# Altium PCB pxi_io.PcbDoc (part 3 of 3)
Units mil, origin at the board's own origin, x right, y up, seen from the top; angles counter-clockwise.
Board outline 6300 x 3935 mil, 2 copper layers (Top Layer, Bottom Layer); 257 components, 420 nets, 1532 pads, 239 vias.
Unrouted connection lines stored in the file: 158.
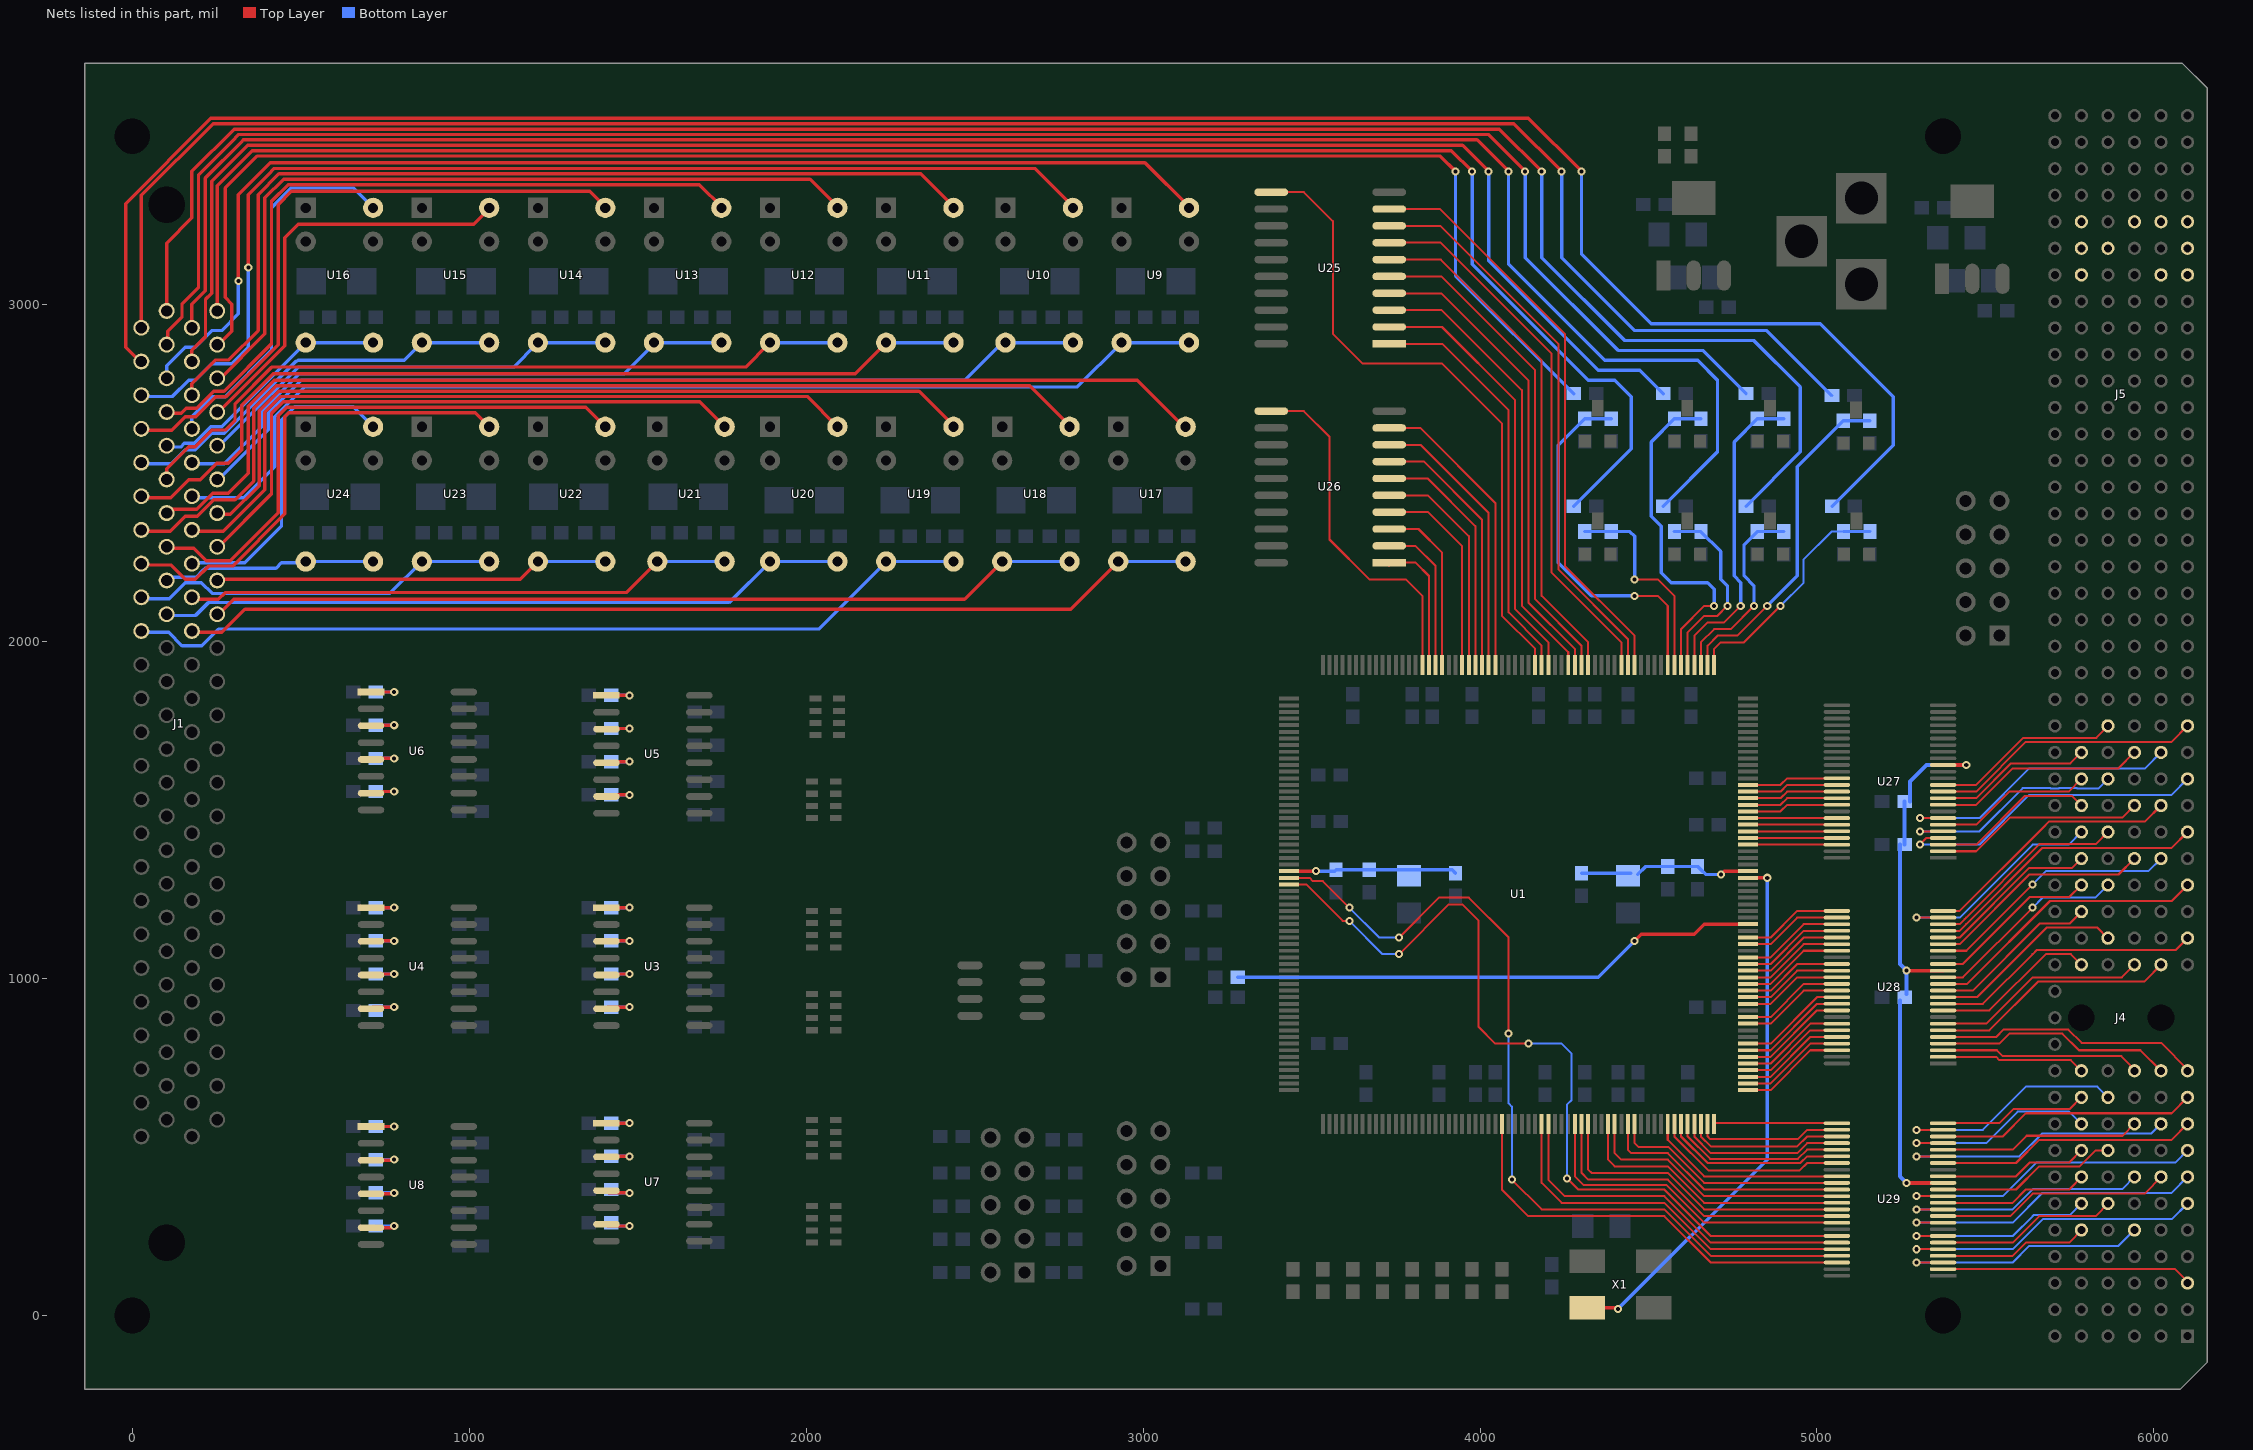
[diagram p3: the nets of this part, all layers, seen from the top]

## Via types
v1: diameter 24, hole 12, Top Layer to Bottom Layer, 232 vias
v2: diameter 36, hole 18, Top Layer to Bottom Layer, 6 vias
v3: diameter 24, hole 12, Top Layer to Bottom Layer, tented bottom, 1 vias

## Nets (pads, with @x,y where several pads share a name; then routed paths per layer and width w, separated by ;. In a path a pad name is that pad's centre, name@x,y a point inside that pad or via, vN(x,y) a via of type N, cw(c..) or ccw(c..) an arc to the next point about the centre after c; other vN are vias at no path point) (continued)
NetR11_2: R11.2 U3.7 | length 126
  Top Layer w10: U3.7@1407.48,910.63 1412.2,915.35 v1(1476.38,915.35)
  Bottom Layer w10: R11.2@1421.26,915.35 v1(1476.38,915.35)
NetR12_2: R12.2 U3.5 | length 125.3
  Top Layer w10: U3.5@1407.48,1010.63 1410.63,1013.78 v1(1476.38,1013.78)
  Bottom Layer w10: R12.2@1421.26,1013.78 v1(1476.38,1013.78)
NetR13_2: R13.2 U3.3 | length 124.7
  Top Layer w10: U3.3@1407.48,1110.63 1409.05,1112.2 v1(1476.38,1112.2)
  Bottom Layer w10: R13.2@1421.26,1112.2 v1(1476.38,1112.2)
NetR14_2: R14.2 U3.1 | length 124
  Top Layer w10: U3.1@1407.48,1210.63 v1(1476.38,1210.63)
  Bottom Layer w10: R14.2@1421.26,1210.63 v1(1476.38,1210.63)
NetR19_2: R19.2 U4.7 | length 130
  Top Layer w10: U4.7@708.66,910.63 713.39,915.35 v1(777.56,915.35)
  Bottom Layer w10: R19.2@722.44,905.51 732.28,915.35 v1(777.56,915.35)
NetR20_2: R20.2 U4.5 | length 125.3
  Top Layer w10: U4.5@708.66,1010.63 711.81,1013.78 v1(777.56,1013.78)
  Bottom Layer w10: R20.2@722.44,1013.78 v1(777.56,1013.78)
NetR21_2: R21.2 U4.3 | length 124.7
  Top Layer w10: U4.3@708.66,1110.63 710.24,1112.2 v1(777.56,1112.2)
  Bottom Layer w10: R21.2@722.44,1112.2 v1(777.56,1112.2)
NetR22_2: R22.2 U4.1 | length 124
  Top Layer w10: U4.1@708.66,1210.63 v1(777.56,1210.63)
  Bottom Layer w10: R22.2@722.44,1210.63 v1(777.56,1210.63)
NetR27_2: R27.2 U5.7 | length 119.3
  Top Layer w10: U5.7@1412.2,1545.28 v1(1476.38,1545.28)
  Bottom Layer w10: R27.2@1421.26,1545.28 v1(1476.38,1545.28)
NetR28_2: R28.2 U5.5 | length 120.9
  Top Layer w10: U5.5@1410.63,1643.7 v1(1476.38,1643.7)
  Bottom Layer w10: R28.2@1421.26,1643.7 v1(1476.38,1643.7)
NetR29_2: R29.2 U5.3 | length 124.7
  Top Layer w10: U5.3@1407.48,1740.55 1409.06,1742.13 v1(1476.38,1742.13)
  Bottom Layer w10: R29.2@1421.26,1742.13 v1(1476.38,1742.13)
NetR30_2: R30.2 U5.1 | length 124
  Top Layer w10: U5.1@1407.48,1840.55 v1(1476.38,1840.55)
  Bottom Layer w10: R30.2@1421.26,1840.55 v1(1476.38,1840.55)
NetR35_2: R35.2 U6.7 | length 126
  Top Layer w10: U6.7@708.66,1550.39 713.39,1555.12 v1(777.56,1555.12)
  Bottom Layer w10: R35.2@722.44,1555.12 v1(777.56,1555.12)
NetR36_2: R36.2 U6.5 | length 125.3
  Top Layer w10: U6.5@708.66,1650.39 711.81,1653.54 v1(777.56,1653.54)
  Bottom Layer w10: R36.2@722.44,1653.54 v1(777.56,1653.54)
NetR37_2: R37.2 U6.3 | length 124.7
  Top Layer w10: U6.3@708.66,1750.39 710.24,1751.97 v1(777.56,1751.97)
  Bottom Layer w10: R37.2@722.44,1751.97 v1(777.56,1751.97)
NetR38_2: R38.2 U6.1 | length 124
  Top Layer w10: U6.1@708.66,1850.39 v1(777.56,1850.39)
  Bottom Layer w10: R38.2@722.44,1850.39 v1(777.56,1850.39)
NetR45_2: R45.2 U7.7 | length 130.2
  Top Layer w10: U7.7@1407.48,270.87 1412.6,265.75 v1(1476.38,265.75)
  Bottom Layer w10: R45.2@1421.26,275.59 1431.1,265.75 v1(1476.38,265.75)
NetR48_2: R48.2 U7.5 | length 130.9
  Top Layer w10: U7.5@1407.48,370.87 1414.17,364.17 v1(1476.38,364.17)
  Bottom Layer w10: R48.2@1421.26,374.02 1431.1,364.17 v1(1476.38,364.17)
NetR51_2: R51.2 U7.3 | length 124.7
  Top Layer w10: U7.3@1407.48,470.87 1409.06,472.44 v1(1476.38,472.44)
  Bottom Layer w10: R51.2@1421.26,472.44 v1(1476.38,472.44)
NetR54_2: R54.2 U7.1 | length 124
  Top Layer w10: U7.1@1407.48,570.87 v1(1476.38,570.87)
  Bottom Layer w10: R54.2@1421.26,570.87 v1(1476.38,570.87)
NetR61_2: R61.2 U8.7 | length 126
  Top Layer w10: U8.7@708.66,261.02 772.83,261.02 v1(777.56,265.75)
  Bottom Layer w10: R61.2@722.44,265.75 v1(777.56,265.75)
NetR64_2: R64.2 U8.5 | length 125.3
  Top Layer w10: U8.5@708.66,361.02 774.41,361.02 v1(777.56,364.17)
  Bottom Layer w10: R64.2@722.44,364.17 v1(777.56,364.17)
NetR67_2: R67.2 U8.3 | length 122.4
  Top Layer w10: U8.3@708.66,461.02 v1@775.98,461.02
  Bottom Layer w10: R67.2@722.44,462.6 v1(777.56,462.6)
NetR70_2: R70.2 U8.1 | length 124
  Top Layer w10: U8.1@708.66,561.02 v1(777.56,561.02)
  Bottom Layer w10: R70.2@722.44,561.02 v1(777.56,561.02)
NetU1_153: U1.153 X1.3 | length 1613
  Top Layer w10: X1.3@4317.98,23.1 4406.03,23.1 v1(4409.45,19.69) ; U1.153@4795.28,1299.21 v1(4852.36,1299.21)
  Bottom Layer w10: v1(4409.45,19.69) 4852.36,462.6 v1(4852.36,1299.21)
NSTATUS: R8.2 U1.146 | length 1579
  Top Layer w10: v1(4458.66,1112.2) 4478.35,1131.89 4635.83,1131.89 4665.35,1161.42 U1.146@4795.28,1161.42
  Bottom Layer w10: R8.2@3281.5,1003.94 4350.39,1003.94 v1(4458.66,1112.2)
O5_1_A: J1.39 U9.5 U9.6 | length 3231.4
  Bottom Layer w10: J1.39@177.17,2427.56 331.1,2427.56 423.23,2519.68 423.23,2667.32 511.81,2755.91 2805.12,2755.91 U9.5@2933.07,2883.86 ; U9.5@2936.22,2887.4 U9.6@3136.22,2887.4
O5_1_B: J1.96 U9.10 | length 3596.8
  Top Layer w10: v1(314.96,3070.87) 314.96,3326.77 397.39,3409.2 ; 393.7,3405.51 409.7,3421.51 3005.65,3421.51 U9.10@3139.76,3287.4
  Bottom Layer w10: J1.96@102.17,2777.56 102.17,2818.7 157.48,2874.02 187.01,2874.02 236.22,2923.23 265.75,2923.23 314.96,2972.44 v1(314.96,3070.87)
O5_2_A: J1.40 U10.5 U10.6 | length 2723.1
  Bottom Layer w10: J1.40@252.17,2477.56 403.54,2628.94 403.54,2677.17 501.97,2775.59 2470.47,2775.59 U10.5@2578.74,2883.86 ; U10.5@2591.73,2887.4 U10.6@2791.73,2887.4
O5_2_B: J1.95 U10.10 | length 3372.5
  Top Layer w10: v1(344.49,3110.24) 344.49,3326.77 403.54,3385.83 ; 410.91,3393.2 403.54,3385.83 ; U10.10@2795.28,3287.4 2678.38,3404.3 422.02,3404.3 403.54,3385.83
  Bottom Layer w10: J1.95@27.17,2727.56 119.29,2727.56 167.32,2775.59 187.01,2775.59 236.22,2824.8 295.28,2824.8 344.49,2874.02 v1(344.49,3110.24)
O5_3_A: J1.89 U11.5 U11.6 | length 2673.9
  Top Layer w10: J1.89@27.17,2427.56 114.57,2427.56 167.32,2480.32 201.51,2480.32 250.72,2529.53 285.43,2529.53 324.8,2568.9 324.8,2701.72 418.36,2795.28 2145.67,2795.28 U11.5@2234.25,2883.86
  Bottom Layer w10: U11.5@2237.4,2887.4 U11.6@2437.4,2887.4
O5_3_B: J1.45 U11.10 | length 2838
  Top Layer w10: J1.45@177.17,2727.56 177.17,2765.75 247.44,2836.02 286.81,2836.02 374.02,2923.23 374.02,3326.77 435.54,3388.3 2340.05,3388.3 2342.52,3385.83 U11.10@2440.94,3287.4
O5_4_A: J1.90 U12.5 U12.6 | length 2205.8
  Top Layer w10: J1.90@102.17,2477.56 102.17,2513.58 167.32,2578.74 187.01,2578.74 236.22,2627.95 275.59,2627.95 305.12,2657.48 305.12,2706.69 413.39,2814.96 1820.87,2814.96 U12.5@1889.76,2883.86
  Bottom Layer w10: U12.5@1892.91,2887.4 U12.6@2092.91,2887.4
O5_4_B: J1.46 U12.10 | length 2362.2
  Top Layer w10: J1.46@252.17,2777.56 257.87,2777.56 393.7,2913.39 393.7,3316.93 449.07,3372.3 2011.56,3372.3 2017.72,3366.14 U12.10@2096.46,3287.4
O5_5_A: J1.41 U13.5 U13.6 | length 1745
  Bottom Layer w10: J1.41@177.17,2527.56 273.62,2527.56 383.86,2637.8 383.86,2684.07 495.07,2795.28 1460.38,2795.28 1545.28,2880.17 U13.5@1545.28,2883.86 ; U13.5@1548.43,2887.4 U13.6@1748.43,2887.4
O5_5_B: J1.94 U13.10 | length 2207.4
  Top Layer w10: J1.94@102.17,2677.56 145.09,2677.56 160.47,2692.94 191.51,2692.94 241.51,2742.94 272.46,2742.94 413.39,2883.86 413.39,3307.09 462.6,3356.3 1683.07,3356.3 U13.10@1751.97,3287.4
O5_6_A: J1.42 U14.5 U14.6 | length 1271.3
  Bottom Layer w10: J1.42@255.91,2578.74 332.17,2655.01 492.13,2814.96 1131.89,2814.96 U14.5@1200.79,2883.86 ; U14.5@1203.94,2887.4 U14.6@1403.94,2887.4
O5_6_B: J1.93 U14.10 | length 1940.6
  Top Layer w10: J1.93@27.17,2627.56 117.72,2627.56 157.48,2667.32 188.52,2667.32 247.57,2726.38 278.53,2726.38 433.07,2880.92 433.07,3297.24 472.44,3336.61 1358.27,3336.61 1368.11,3326.77 ; 1366.48,3328.4 1368.11,3326.77 ; U14.10@1407.48,3287.4 1368.11,3326.77
O5_7_A: J1.91 U15.5 U15.6 | length 1176.7
  Bottom Layer w10: J1.91@27.17,2527.56 116.14,2527.56 157.48,2568.9 187.01,2568.9 236.22,2618.11 272.65,2618.11 487.57,2833.03 490.51,2833.03 492.13,2834.65 807.09,2834.65 U15.5@856.3,2883.86 ; U15.5@859.45,2887.4 U15.6@1059.45,2887.4
O5_7_B: J1.44 U15.10 | length 1251.3
  Top Layer w10: J1.44@252.25,2677.47 452.76,2877.97 452.76,3198.82 492.13,3238.19 1013.78,3238.19 U15.10@1062.99,3287.4
O5_8_A: J1.92 U16.5 U16.6 | length 734
  Bottom Layer w10: J1.92@102.17,2577.56 143.51,2577.56 154.54,2588.58 184.07,2588.58 233.28,2637.8 265.75,2637.8 505.65,2877.7 U16.5@511.81,2877.7 ; U16.5@514.96,2887.4 U16.6@714.96,2887.4
O5_8_B: J1.43 U16.10 | length 1131.2
  Bottom Layer w10: J1.43@177.17,2627.56 177.17,2667.32 236.22,2726.38 275.59,2726.38 413.39,2864.17 413.39,3287.4 472.44,3346.46 655.91,3346.46 U16.10@714.96,3287.4
O5_D1: U1.193 U25.9 | length 1743
  Top Layer w6: U25.9@3730.31,3283.86 3881.5,3283.86 4251.97,2913.39 4251.97,2224.41 4458.66,2017.72 U1.193@4458.66,1931.1
O5_D2: U1.194 U25.8 | length 1685.3
  Top Layer w6: U25.8@3730.31,3233.86 3882.28,3233.86 4232.28,2883.86 4232.28,2214.57 4438.98,2007.87 U1.194@4438.98,1931.1
O5_D3: U1.195 U25.7 | length 1631
  Top Layer w6: U25.7@3730.31,3179.13 U25.7@3732.68,3181.5 ; U25.7@3730.31,3183.86 3883.07,3183.86 4212.6,2854.33 4212.6,2204.72 4419.29,1998.03 U1.195@4419.29,1931.1
O5_D4: U1.200 U25.6 | length 1537.3
  Top Layer w6: U25.6@3730.31,3133.86 3883.86,3133.86 4183.07,2834.65 4183.07,2135.83 4320.87,1998.03 U1.200@4320.87,1931.1
O5_D5: U1.201 U25.5 | length 1479.6
  Top Layer w6: U25.5@3730.31,3083.86 3884.65,3083.86 4163.39,2805.12 4163.39,2125.98 4301.18,1988.19 U1.201@4301.18,1931.1
O5_D6: U1.202 U25.4 | length 1421.9
  Top Layer w6: U25.4@3730.31,3033.86 3885.43,3033.86 4143.7,2775.59 4143.7,2116.14 4281.5,1978.35 U1.202@4281.5,1931.1
O5_D7: U1.203 U25.3 | length 1364.2
  Top Layer w6: U25.3@3730.31,2983.86 3886.22,2983.86 4124.02,2746.06 4124.02,2106.3 4261.81,1968.5 U1.203@4261.81,1931.1
O5_D8: U1.206 U25.2 | length 1290.2
  Top Layer w6: U25.2@3730.31,2933.86 3887.01,2933.86 4104.33,2716.54 4104.33,2096.46 4202.76,1998.03 U1.206@4202.76,1931.1
O5_LE: U1.208 U25.11 | length 1922.2
  Top Layer w6: U25.11@3380.31,3333.86 3477.17,3333.86 3562.99,3248.03 3562.99,2913.39 3651.57,2824.8 3887.8,2824.8 4064.96,2647.64 4064.96,2076.77 4163.39,1978.35 U1.208@4163.39,1931.1
O5_OE: U1.207 U25.1 | length 1232.5
  Top Layer w6: U25.1@3730.31,2883.86 3887.8,2883.86 4084.65,2687.01 4084.65,2086.61 4183.07,1988.19 U1.207@4183.07,1931.1
O27_1_A: J1.31 U17.5 U17.6 | length 3032.2
  Top Layer w10: J1.31@177.17,2027.56 265.75,2027.56 285.43,2047.24 ; 285.06,2046.87 334.65,2096.46 2785.43,2096.46 U17.5@2923.23,2234.25
  Bottom Layer w10: U17.5@2926.38,2237.8 U17.6@3126.38,2237.8
O27_1_B: J1.88 U17.10 | length 3356.3
  Top Layer w10: J1.88@102.17,2377.56 117.54,2392.94 191.51,2392.94 239.51,2440.94 285.43,2440.94 344.49,2500 344.49,2698.78 421.3,2775.59 2982.28,2775.59 U17.10@3120.08,2637.8
O27_2_A: J1.32 U18.5 U18.6 | length 2596.4
  Top Layer w10: J1.32@252.17,2076.77 301.38,2125.98 2470.08,2125.98 U18.5@2581.89,2237.8
  Bottom Layer w10: U18.5@2581.89,2237.8 U18.6@2781.89,2237.8
O27_2_B: J1.87 U18.10 | length 3121.2
  Top Layer w10: J1.87@27.17,2327.56 112.99,2327.56 157.48,2372.05 193.24,2372.05 242.46,2421.26 305.12,2421.26 360.49,2476.63 360.49,2692.15 427.93,2759.59 2125.98,2759.59 ; 2133.23,2759.59 2125.98,2759.59 ; U18.10@2785.43,2637.8 2663.64,2759.59 2125.98,2759.59
O27_3_A: J1.81 U19.5 U19.6 | length 2529.9
  Bottom Layer w10: J1.81@27.17,2027.56 108.27,2027.56 147.64,1988.19 206.69,1988.19 255.91,2037.4 2037.01,2037.4 U19.5@2237.4,2237.8 U19.6@2437.4,2237.8
O27_3_B: J1.38 U19.10 | length 2514.5
  Top Layer w10: J1.38@252.17,2377.56 290.94,2377.56 376.49,2463.1 376.49,2685.52 434.56,2743.59 2335.15,2743.59 U19.10@2440.94,2637.8
O27_4_A: J1.82 U20.5 U20.6 | length 2057.1
  Bottom Layer w10: J1.82@102.17,2077.56 187.8,2077.56 226.38,2116.14 1771.26,2116.14 U20.5@1892.91,2237.8 U20.6@2092.91,2237.8
O27_4_B: J1.37 U20.10 | length 2253
  Top Layer w10: J1.37@177.17,2327.56 270.47,2327.56 393.7,2450.79 393.7,2680.11 441.18,2727.59 2003.12,2727.59 U20.10@2092.91,2637.8
O27_5_A: J1.33 U21.5 U21.6 | length 1631.5
  Top Layer w10: J1.33@177.17,2135.83 187.01,2125.98 255.91,2125.98 275.59,2145.67 1466.14,2145.67 U21.5@1558.27,2237.8
  Bottom Layer w10: U21.5@1558.27,2237.8 U21.6@1758.27,2237.8
O27_5_B: J1.36 U21.10 | length 1856.1
  Top Layer w10: J1.36@252.17,2277.56 413.39,2438.78 413.39,2677.17 447.81,2711.59 1684.47,2711.59 U21.10@1758.27,2637.8
O27_6_A: J1.34 U22.5 U22.6 | length 1169.9
  Top Layer w10: J1.34@255.91,2185.04 1151.18,2185.04 U22.5@1203.94,2237.8
  Bottom Layer w10: U22.5@1203.94,2237.8 U22.6@1403.94,2237.8
O27_6_B: J1.86 U22.10 | length 1698.6
  Top Layer w10: J1.86@102.17,2277.56 183.07,2277.56 220.22,2240.41 291.59,2240.41 433.07,2381.89 433.07,2670.27 458.4,2695.59 1346.14,2695.59 U22.10@1403.94,2637.8
O27_7_A: J1.83 U23.5 U23.6 | length 1104.7
  Bottom Layer w10: J1.83@27.17,2127.56 109.84,2127.56 157.48,2175.2 205.56,2175.2 237.82,2142.94 764.59,2142.94 U23.5@859.45,2237.8 U23.6@1059.45,2237.8
O27_7_B: J1.85 U23.10 | length 1441
  Top Layer w10: J1.85@27.17,2227.56 114.96,2227.56 157.48,2185.04 187.01,2185.04 226.38,2224.41 298.22,2224.41 452.76,2378.95 452.76,2667.32 465.02,2679.59 1017.65,2679.59 U23.10@1059.45,2637.8
O27_8_A: J1.84 U24.5 U24.6 | length 637.7
  Bottom Layer w10: J1.84@102.17,2177.56 115.8,2191.2 189.77,2191.2 209.91,2211.34 ; 213.14,2214.57 209.91,2211.34 ; U24.5@511.81,2234.25 442.91,2234.25 426.91,2218.25 216.82,2218.25 209.91,2211.34 ; U24.5@514.96,2237.8 U24.6@714.96,2237.8
O27_8_B: J1.35 U24.10 | length 931.7
  Bottom Layer w10: J1.35@183.86,2234.25 334.65,2234.25 442.91,2342.52 442.91,2657.48 482.28,2696.85 655.91,2696.85 U24.10@714.96,2637.8
O27_D1: U1.214 U26.9 | length 887.6
  Top Layer w6: U26.9@3730.31,2634.25 3822.44,2634.25 4045.28,2411.42 U1.214@4045.28,1931.1
O27_D2: U1.215 U26.8 | length 829.9
  Top Layer w6: U26.8@3730.31,2584.25 3823.23,2584.25 4025.59,2381.89 U1.215@4025.59,1931.1
O27_D3: U1.216 U26.7 | length 778
  Top Layer w6: U26.7@3730.31,2534.25 3833.86,2534.25 4005.91,2362.2 U1.216@4005.91,1931.1
O27_D4: U1.217 U26.6 | length 726
  Top Layer w6: U26.6@3730.31,2484.25 3844.49,2484.25 3986.22,2342.52 U1.217@3986.22,1931.1
O27_D5: U1.218 U26.5 | length 668.3
  Top Layer w6: U26.5@3730.31,2434.25 3845.28,2434.25 3966.54,2312.99 U1.218@3966.54,1931.1
O27_D6: U1.219 U26.4 | length 610.6
  Top Layer w6: U26.4@3730.31,2384.25 3846.06,2384.25 3946.85,2283.46 U1.219@3946.85,1931.1
O27_D7: U1.222 U26.3 | length 519.3
  Top Layer w6: U26.3@3730.31,2334.25 3817.32,2334.25 3887.8,2263.78 U1.222@3887.8,1931.1
O27_D8: U1.223 U26.2 | length 455.9
  Top Layer w6: U26.2@3730.31,2284.25 3808.27,2284.25 3868.11,2224.41 U1.223@3868.11,1931.1
O27_LE: U1.225 U26.11 | length 1059
  Top Layer w6: U26.11@3380.31,2684.25 3477.17,2684.25 3553.15,2608.27 3553.15,2303.15 3671.26,2185.04 3779.53,2185.04 3828.74,2135.83 U1.225@3828.74,1931.1
O27_OE: U1.224 U26.1 | length 398.2
  Top Layer w6: U26.1@3730.31,2234.25 3809.06,2234.25 3848.43,2194.88 U1.224@3848.43,1931.1
OC5_1: J1.97 R101.2 | length 6733.1
  Top Layer w10: J1.97@29.53,2824.8 -19.68,2874.02 -19.68,3300.19 233.33,3553.2 4143.65,3553.2 v1(4301.18,3395.67)
  Bottom Layer w10: v1(4301.18,3395.67) 4301.18,3149.61 4507.87,2942.91 5009.84,2942.91 5226.38,2726.38 5226.38,2582.68 R101.2@5045.28,2401.57
OC5_2: J1.99 R103.2 | length 5962.7
  Top Layer w10: J1.99@27.17,2951.18 27.17,3324.41 239.91,3537.15 391.61,3537.15 391.65,3537.2 4100.6,3537.2 v1(4242.13,3395.67)
  Bottom Layer w10: v1(4242.13,3395.67) 4242.13,3139.76 4458.66,2923.23 4851.56,2923.23 R103.2@5044.42,2730.37
OC5_3: J1.100 R105.2 | length 6139.3
  Top Layer w10: J1.100@102.17,3001.18 102.17,3182.87 177.17,3257.87 177.17,3395.67 302.65,3521.15 398.23,3521.15 398.28,3521.2 4057.54,3521.2 v1(4183.07,3395.67)
  Bottom Layer w10: v1(4183.07,3395.67) 4183.07,3139.76 4429.13,2893.7 4812.99,2893.7 4950.79,2755.91 4950.79,2562.99 R105.2@4789.37,2401.57
OC5_4: J1.98 R107.2 | length 5632.7
  Top Layer w10: J1.98@105.91,2901.18 105.91,2920.87 147.64,2962.6 147.64,3001.97 196.85,3051.18 196.85,3385.83 295.28,3484.25 316.17,3505.15 404.86,3505.15 404.91,3505.2 4024.33,3505.2 v1(4133.86,3395.67)
  Bottom Layer w10: v1(4133.86,3395.67) 4133.86,3139.76 4409.45,2864.17 4661.42,2864.17 R107.2@4789.37,2736.22
OC5_5: J1.49 R109.2 | length 5878
  Top Layer w10: J1.49@177.17,2951.18 177.17,3001.97 216.54,3041.34 216.54,3375.98 324.8,3484.25 329.7,3489.15 411.49,3489.15 411.53,3489.2 3897.63,3489.2 ; 3901.52,3489.2 3897.63,3489.2 ; v1(4084.65,3395.67) 3991.12,3489.2 3897.63,3489.2
  Bottom Layer w10: v1(4084.65,3395.67) 4084.65,3120.08 4370.08,2834.65 4645.67,2834.65 4704.72,2775.59 4704.72,2562.99 R109.2@4543.31,2401.57
OC5_6: J1.47 R111.2 | length 5353
  Top Layer w10: J1.47@178,2852.02 177.17,2851.18 177.17,2864.17 217.54,2904.55 217.54,3015.52 236.17,3034.14 236.17,3366.09 343.23,3473.15 418.11,3473.15 418.16,3473.2 3948.06,3473.2 v1(4025.59,3395.67)
  Bottom Layer w10: v1(4025.59,3395.67) 4025.59,3129.92 4350.39,2805.12 4474.41,2805.12 R111.2@4543.31,2736.22
OC5_7: J1.50 R113.2 | length 5474.9
  Top Layer w10: J1.50@252.17,2977.56 252.17,3352.56 324.8,3425.2 356.76,3457.15 424.74,3457.15 424.79,3457.2 3914.85,3457.2 v1(3976.38,3395.67)
  Bottom Layer w10: v1(3976.38,3395.67) 3976.38,3120.08 4320.87,2775.59 4399.61,2775.59 4448.82,2726.38 4448.82,2572.83 R113.2@4277.56,2401.57
OC5_8: J1.48 R115.2 | length 5058.4
  Top Layer w10: J1.48@252.17,2877.56 295.28,2920.67 295.28,3001.97 275.59,3021.65 275.59,3346.46 370.28,3441.15 431.37,3441.15 431.42,3441.2 3881.64,3441.2 v1(3927.17,3395.67)
  Bottom Layer w10: 3927.17,3346.46 v1(3927.17,3395.67) 3927.17,3086.61 R115.2@4277.56,2736.22
OC5_D1: C81.2 R100.1 U1.181 | length 694.5
  Top Layer w6: U1.181@4694.88,1931.1 4694.88,1978.35 4714.57,1998.03 4783.46,1998.03 v1(4891.73,2106.3)
  Bottom Layer w6: v1(4891.73,2106.3) 4960.63,2175.2 4960.63,2244.09 5043.31,2326.77 C81.2@5078.74,2326.77
  Bottom Layer w10: C81.2@5078.74,2326.77 R100.1@5157.48,2326.77
OC5_D2: C82.2 R102.1 U1.182 | length 1004.6
  Top Layer w6: U1.182@4675.2,1931.1 4675.2,1988.19 4704.72,2017.72 4763.78,2017.72 v1(4852.36,2106.3)
  Bottom Layer w10: v1(4852.36,2106.3) 4940.94,2194.88 4940.94,2518.63 C82.2@5077.88,2655.57 R102.1@5156.62,2655.57
OC5_D3: C83.2 R104.1 U1.183 | length 597
  Top Layer w6: U1.183@4655.51,1931.1 4655.51,1998.03 4694.88,2037.4 4744.09,2037.4 v1(4812.99,2106.3)
  Bottom Layer w10: v1(4812.99,2106.3) 4812.99,2165.35 4783.46,2194.88 4783.46,2287.4 C83.2@4822.83,2326.77 R104.1@4901.57,2326.77
OC5_D4: C84.2 R106.1 U1.184 | length 931.7
  Top Layer w6: U1.184@4635.83,1931.1 4635.83,2017.72 4675.2,2057.09 4724.41,2057.09 v1(4773.62,2106.3)
  Bottom Layer w10: v1(4773.62,2106.3) 4773.62,2175.2 4753.94,2194.88 4753.94,2592.52 C84.2@4822.83,2661.42 R106.1@4901.57,2661.42
OC5_D5: C85.2 R108.1 U1.185 | length 579
  Top Layer w6: U1.185@4616.14,1931.1 4616.14,2027.56 4665.35,2076.77 4704.72,2076.77 v1(4734.25,2106.3)
  Bottom Layer w10: C85.2@4576.77,2326.77 R108.1@4655.51,2326.77 4714.57,2267.72 4714.57,2185.04 4734.25,2165.35 v1(4734.25,2106.3)
OC5_D6: C86.2 R110.1 U1.186 | length 1036.5
  Top Layer w6: U1.186@4596.46,1931.1 4596.46,2037.4 4665.35,2106.3 v1(4694.88,2106.3)
  Bottom Layer w10: R110.1@4655.51,2661.42 C86.2@4576.77,2661.42 4507.87,2592.52 4507.87,2372.05 4537.4,2342.52 4537.4,2204.72 4566.93,2175.2 4675.2,2175.2 4694.88,2155.51 v1(4694.88,2106.3)
OC5_D7: C87.2 R112.1 U1.187 | length 624.5
  Top Layer w6: v1(4458.66,2185.04) 4527.56,2185.04 4576.77,2135.83 U1.187@4576.77,1931.1
  Bottom Layer w10: C87.2@4311.02,2326.77 R112.1@4389.76,2326.77 4444.88,2326.77 4458.66,2312.99 v1(4458.66,2185.04)
OC5_D8: C88.2 R114.1 U1.188 | length 1091.5
  Top Layer w6: v1(4458.66,2135.83) 4527.56,2135.83 4557.09,2106.3 U1.188@4557.09,1931.1
  Bottom Layer w10: R114.1@4389.76,2661.42 C88.2@4311.02,2661.42 4232.28,2582.68 4232.28,2234.25 4330.71,2135.83 v1(4458.66,2135.83)
P_AD0: U1.167 U27.36 | length 271.9
  Top Layer w6: U1.167@4795.28,1574.8 4891.73,1574.8 4911.42,1594.49 U27.36@5059.06,1594.49
P_AD1: U1.166 U27.37 | length 271.9
  Top Layer w6: U1.166@4795.28,1555.12 4891.73,1555.12 4911.42,1574.8 U27.37@5059.06,1574.8
P_AD2: U1.165 U27.38 | length 271.9
  Top Layer w6: U1.165@4795.28,1535.43 4891.73,1535.43 4911.42,1555.12 U27.38@5059.06,1555.12
P_AD3: U1.164 U27.39 | length 271.9
  Top Layer w6: U1.164@4795.28,1515.75 4891.73,1515.75 4911.42,1535.43 U27.39@5059.06,1535.43
P_AD4: U1.163 U27.40 | length 271.9
  Top Layer w6: U1.163@4795.28,1496.06 4891.73,1496.06 4911.42,1515.75 U27.40@5059.06,1515.75
P_AD5: U1.162 U27.42 | length 263.8
  Top Layer w6: U1.162@4795.28,1476.38 U27.42@5059.06,1476.38
P_AD6: U1.161 U27.43 | length 263.8
  Top Layer w6: U1.161@4795.28,1456.69 U27.43@5059.06,1456.69
P_AD7: U1.160 U27.44 | length 263.8
  Top Layer w6: U1.160@4795.28,1437.01 U27.44@5059.06,1437.01
P_AD8: U1.158 U27.46 | length 263.8
  Top Layer w6: U1.158@4795.28,1397.64 U27.46@5059.06,1397.64
P_AD9: U1.144 U28.25 | length 296.4
  Top Layer w6: U1.144@4795.28,1122.05 4862.2,1122.05 4940.94,1200.79 U28.25@5059.06,1200.79
P_AD10: U1.143 U28.26 | length 296.4
  Top Layer w6: U1.143@4795.28,1102.36 4862.2,1102.36 4940.94,1181.1 U28.26@5059.06,1181.1
P_AD11: U1.141 U28.27 | length 304.5
  Top Layer w6: U1.141@4795.28,1062.99 4862.2,1062.99 4960.63,1161.42 U28.27@5059.06,1161.42
P_AD12: U1.140 U28.28 | length 304.5
  Top Layer w6: U1.140@4795.28,1043.31 4862.2,1043.31 4960.63,1141.73 U28.28@5059.06,1141.73
P_AD13: U1.139 U28.29 | length 304.5
  Top Layer w6: U1.139@4795.28,1023.62 4862.2,1023.62 4960.63,1122.05 U28.29@5059.06,1122.05
P_AD14: U1.138 U28.30 | length 304.5
  Top Layer w6: U1.138@4795.28,1003.94 4862.2,1003.94 4960.63,1102.36 U28.30@5059.06,1102.36
P_AD15: U1.137 U28.31 | length 304.5
  Top Layer w6: U1.137@4795.28,984.25 4862.2,984.25 4960.63,1082.68 U28.31@5059.06,1082.68
P_AD16: U1.122 U28.45 | length 312.7
  Top Layer w6: U1.122@4795.28,688.98 4862.2,688.98 4980.31,807.09 5000,807.09 U28.45@5059.06,807.09
P_AD17: U1.123 U28.44 | length 312.7
  Top Layer w6: U1.123@4795.28,708.66 4862.2,708.66 4980.31,826.77 5000,826.77 U28.44@5059.06,826.77
P_AD18: U1.124 U28.43 | length 312.7
  Top Layer w6: U1.124@4795.28,728.35 4862.2,728.35 4980.31,846.46 5000,846.46 U28.43@5059.06,846.46
P_AD19: U1.120 U29.25 | length 364.2
  Top Layer w6: U1.120@4694.88,570.87 U29.25@5059.06,570.87
P_AD20: U1.119 U29.26 | length 435.8
  Top Layer w6: U1.119@4675.2,568.9 4675.2,531.5 4682.88,523.81 4943.1,523.81 4970.47,551.18 U29.26@5059.06,551.18
P_AD21: U1.118 U29.27 | length 455.6
  Top Layer w6: U1.118@4655.51,568.9 4655.51,531.5 4685.04,501.97 4940.94,501.97 4970.47,531.5 U29.27@5049.21,531.5
P_AD22: U1.117 U29.28 | length 493.2
  Top Layer w6: U1.117@4635.83,568.9 4635.83,531.5 4685.04,482.28 4940.94,482.28 4970.47,511.81 4980.31,511.81 U29.28@5059.06,511.81
P_AD23: U1.116 U29.29 | length 519.3
  Top Layer w6: U1.116@4616.14,568.9 4616.14,531.5 4682.88,464.76 4943.1,464.76 4970.47,492.13 4980.31,492.13 U29.29@5059.06,492.13
P_AD24: U1.113 U29.33 | length 594.1
  Top Layer w6: U1.113@4557.09,568.9 4557.09,521.65 4665.35,413.39 4980.31,413.39 U29.33@5059.06,413.39
P_AD25: U1.108 U29.34 | length 706.4
  Top Layer w6: U1.108@4458.66,568.9 4458.66,511.81 4469.92,500.55 4558.07,500.55 4664.92,393.7 4980.31,393.7 U29.34@5059.06,393.7
P_AD26: U1.107 U29.35 | length 745.8
  Top Layer w6: U1.107@4438.98,568.9 4438.98,492.13 4448.82,482.28 4557.09,482.28 4665.35,374.02 4980.31,374.02 U29.35@5059.06,374.02
P_AD27: U1.105 U29.36 | length 799.1
  Top Layer w6: U1.105@4399.61,568.9 4399.61,482.28 4419.29,462.6 4557.09,462.6 4665.35,354.33 4980.31,354.33 U29.36@5059.06,354.33
P_AD28: U1.104 U29.37 | length 838.4
  Top Layer w6: U1.104@4379.92,568.9 4379.92,462.6 4399.61,442.91 4557.09,442.91 4665.35,334.65 4980.31,334.65 U29.37@5059.06,334.65
P_AD29: U1.101 U29.38 | length 922.9
  Top Layer w6: U1.101@4320.87,568.9 4320.87,433.07 4330.71,423.23 4557.09,423.23 4665.35,314.96 4980.31,314.96 U29.38@5059.06,314.96
P_AD30: U1.100 U29.39 | length 956.5
  Top Layer w6: U1.100@4301.18,568.9 4301.18,423.23 4320.87,403.54 4557.09,403.54 4665.35,295.28 4980.31,295.28 U29.39@5059.06,295.28
P_AD31: U1.99 U29.40 | length 990.1
  Top Layer w6: U1.99@4281.5,568.9 4281.5,413.39 4306.81,388.07 4552.87,388.07 4665.35,275.59 4980.31,275.59 U29.40@5059.06,275.59
P_CBE0: U1.159 U27.45 | length 263.8
  Top Layer w6: U1.159@4795.28,1417.32 U27.45@5059.06,1417.32
P_CBE1: U1.136 U28.33 | length 296.4
  Top Layer w6: U1.136@4795.28,964.57 4862.2,964.57 4940.94,1043.31 U28.33@5059.06,1043.31
P_CBE2: U1.121 U28.46 | length 312.7
  Top Layer w6: U1.121@4795.28,669.29 4862.2,669.29 4980.31,787.4 5000,787.4 U28.46@5059.06,787.4
P_CBE3: U1.114 U29.31 | length 570.4
  Top Layer w6: U1.114@4576.77,568.9 4576.77,531.5 4677.35,430.91 4948.63,430.91 4970.47,452.76 4980.31,452.76 U29.31@5059.06,452.76
P_CLK: U1.29 U29.42 | length 2600.6
  Top Layer w6: U1.29@3433.07,1279.53 3484.25,1279.53 3592.52,1171.26 v1(3612.2,1171.26) ; v1(3759.84,1072.83) 3907.48,1220.47 3946.85,1220.47 3996.06,1171.26 3996.06,856.3 4045.28,807.09 v1(4143.7,807.09) ; v1(4258.6,406.76) 4291.34,374.02 4547.24,374.02 4685.04,236.22 4980.31,236.22 U29.42@5059.06,236.22
  Bottom Layer w6: v1(3612.2,1171.26) 3710.63,1072.83 v1(3759.84,1072.83) ; v1(4143.7,807.09) 4242.13,807.09 4271.65,777.56 4271.65,639.76 4258.6,626.71 v1(4258.6,406.76)
P_DEVSEL: U1.128 U28.38 | length 320.9
  Top Layer w6: U1.128@4795.28,807.09 4862.2,807.09 5000,944.88 5019.69,944.88 U28.38@5059.06,944.88
P_FRAME: U1.125 U28.42 | length 312.7
  Top Layer w6: U1.125@4795.28,748.03 4862.2,748.03 4980.31,866.14 5000,866.14 U28.42@5059.06,866.14
P_GNT: U1.94 U29.44 | length 1132.7
  Top Layer w6: U1.94@4183.07,568.9 4183.07,393.7 4242.13,334.65 4547.24,334.65 4685.04,196.85 4980.31,196.85 U29.44@5059.06,196.85
P_IDSEL: U1.115 U29.30 | length 540.8
  Top Layer w6: U1.115@4596.46,568.9 4596.46,531.5 4675.2,452.76 4950.79,452.76 4970.47,472.44 4980.31,472.44 U29.30@5059.06,472.44
P_INTA: U1.88 U29.46 | length 1280.7
  Top Layer w6: U1.88@4064.96,568.9 4064.96,374.02 4143.7,295.28 4547.24,295.28 4685.04,157.48 4980.31,157.48 U29.46@5059.06,157.48 U29.46@5057.64,156.06
P_IRDY: U1.126 U28.40 | length 360.2
  Top Layer w6: U1.126@4795.28,767.72 4862.2,767.72 5000,905.51 U28.40@5059.06,905.51 5019.68,905.51
P_PAR: U1.135 U28.34 | length 296.4
  Top Layer w6: U1.135@4795.28,944.88 4862.2,944.88 4940.94,1023.62 U28.34@5059.06,1023.62
P_PERR: U1.132 U28.36 | length 304.5
  Top Layer w6: U1.132@4795.28,885.83 4862.2,885.83 4960.63,984.25 U28.36@5059.06,984.25
P_REQ: U1.95 U29.43 | length 1099.1
  Top Layer w6: U1.95@4202.76,568.9 4202.76,403.54 4251.97,354.33 4547.24,354.33 4685.04,216.54 4980.31,216.54 U29.43@5059.06,216.54
P_RST: U1.28 U29.45 | length 2603.7
  Top Layer w6: U1.28@3433.07,1299.21 3494.09,1299.21 3503.94,1289.37 3533.46,1289.37 v1(3612.2,1210.63) ; v1@3759.84,1122.05 3877.95,1240.16 3966.54,1240.16 4084.65,1122.05 v1(4084.65,836.61) ; v1(4094.49,403.54) 4183.07,314.96 4547.24,314.96 4685.04,177.17 4980.31,177.17 U29.45@5059.06,177.17
  Bottom Layer w6: v1(3612.2,1210.63) 3700.85,1121.99 v1(3759.78,1121.99) ; v1(4084.65,836.61) 4084.65,629.92 4094.49,620.08 v1(4094.49,403.54)
P_SERR: U1.134 U28.35 | length 296.4
  Top Layer w6: U1.134@4795.28,925.2 4862.2,925.2 4940.94,1003.94 U28.35@5059.06,1003.94
P_STOP: U1.131 U28.37 | length 304.5
  Top Layer w6: U1.131@4795.28,866.14 4862.2,866.14 4960.63,964.57 U28.37@5059.06,964.57
P_TRDY: U1.127 U28.39 | length 320.9
  Top Layer w6: U1.127@4795.28,787.4 4862.2,787.4 5000,925.2 5019.69,925.2 U28.39@5059.06,925.2
PXI_AD0: J4.D24 U27.12 | length 565.5
  Top Layer w6: U27.12@5374.02,1574.8 5472.44,1574.8 5612.39,1714.76 5828.93,1714.76 J4.D24@5866.14,1751.97
PXI_AD1: J4.A24 U27.11 | length 806.3
  Top Layer w6: U27.11@5374.02,1555.12 5472.44,1555.12 5620.08,1702.76 6052.36,1702.76 J4.A24@6099.61,1750
PXI_AD2: J4.E23 U27.10 | length 471.6
  Top Layer w6: U27.10@5374.02,1535.43 5472.44,1535.43 5575.79,1638.78 5752.17,1638.78 J4.E23@5784.65,1671.26
  Bottom Layer w6: J4.E23@5784.65,1671.26 J4.E23@5784.65,1675.98
PXI_AD3: J4.C23 U27.9 | length 632.5
  Top Layer w6: U27.9@5374.02,1515.75 5472.44,1515.75 5580.71,1624.02 5894.88,1624.02 J4.C23@5942.13,1671.26
PXI_AD4: J4.B23 U27.7 | length 865.4
  Top Layer w6: v1(5305.12,1476.38) U27.7@5374.02,1476.38
  Bottom Layer w6: v1(5305.12,1476.38) 5482.28,1476.38 5629.92,1624.02 5973.62,1624.02 J4.B23@6020.87,1671.26
PXI_AD5: J4.E22 U27.6 | length 466.9
  Top Layer w6: U27.6@5374.02,1456.69 5472.44,1456.69 5570.87,1555.12 5747.24,1555.12 J4.E22@5784.65,1592.52
PXI_AD6: J4.D22 U27.5 | length 708.4
  Top Layer w6: v1(5305.12,1437.01) U27.5@5374.02,1437.01
  Bottom Layer w6: v1(5305.12,1437.01) 5482.28,1437.01 5610.24,1564.96 5692.9,1564.96 5694.02,1563.83 5717.79,1563.83 5718.91,1564.96 5771.64,1564.96 5772.76,1563.83 5834.7,1563.83 J4.D22@5863.39,1592.52 J4.D22@5848.43,1592.52
PXI_AD7: J4.A22 U27.4 | length 952.3
  Top Layer w6: v1(5305.12,1397.64) 5324.8,1417.32 U27.4@5374.02,1417.32
  Bottom Layer w6: v1(5305.12,1397.64) 5482.28,1397.64 5629.92,1545.28 6052.36,1545.28 J4.A22@6099.61,1592.52
PXI_AD8: J4.C21 U27.2 | length 624.4
  Top Layer w6: U27.2@5374.02,1377.95 5472.44,1377.95 5573.02,1478.54 5906.88,1478.54 J4.C21@5942.13,1513.78
PXI_AD9: J4.B21 U28.24 | length 776.5
  Top Layer w6: U28.24@5374.02,1200.79 5423.23,1200.79 5669.36,1446.92 5688.98,1466.54 5973.62,1466.54 J4.B21@6020.87,1513.78
PXI_AD10: J4.E20 U28.23 | length 673.3
  Top Layer w6: v1(5295.28,1181.1) U28.23@5374.02,1181.1
  Bottom Layer w6: v1(5295.28,1181.1) 5423.23,1181.1 5639.76,1397.64 5747.24,1397.64 J4.E20@5784.65,1435.04
PXI_AD11: J4.D20 U28.22 | length 609.8
  Top Layer w6: U28.22@5374.02,1161.42 5423.23,1161.42 5442.91,1181.1 ; 5437.99,1176.18 5442.91,1181.1 ; J4.D20@5863.39,1435.04 5828.14,1399.8 5669.29,1399.8 5661.61,1399.8 5661.61,1399.62 5443.08,1181.1 5442.91,1181.1
PXI_AD12: J4.A20 U28.21 | length 854
  Top Layer w6: U28.21@5374.02,1141.73 5423.23,1141.73 5442.91,1161.41 ; 5437.99,1156.5 5442.91,1161.41 ; J4.A20@6099.61,1435.04 6052.36,1387.8 5669.29,1387.8 5442.91,1161.41
PXI_AD13: J4.E19 U28.20 | length 507.7
  Top Layer w6: U28.20@5374.02,1122.05 5423.23,1122.05 5628.8,1327.61 5755.96,1327.61 J4.E19@5784.65,1356.3
PXI_AD14: J4.C19 U28.19 | length 673.3
  Top Layer w6: U28.19@5374.02,1102.36 5423.23,1102.36 5629.92,1309.06 5894.88,1309.06 J4.C19@5942.13,1356.3
PXI_AD15: J4.B19 U28.18 | length 760.2
  Top Layer w6: U28.18@5374.02,1082.68 5442.91,1082.68 v1(5639.76,1279.53)
  Bottom Layer w6: v1(5639.76,1279.53) 5679.13,1318.9 5983.46,1318.9 J4.B19@6020.87,1356.3
PXI_AD16: J4.C11 U28.3 | length 600.4
  Top Layer w6: U28.3@5374.02,787.4 5533.65,787.4 5551.18,769.87 5903.35,769.87 J4.C11@5944.88,728.35 ; J4.C11@5937.01,726.38 J4.C11@5942.13,726.38
PXI_AD17: J4.B11 U28.4 | length 704.7
  Top Layer w6: U28.4@5374.02,807.09 5541.34,807.09 5570.87,836.61 5728.35,836.61 5777.56,787.4 5959.84,787.4 J4.B11@6020.87,726.38
PXI_AD18: J4.A11 U28.5 | length 792.3
  Top Layer w6: U28.5@5374.02,826.77 5531.5,826.77 5553.34,848.61 5745.87,848.61 5785.24,809.24 6021.46,809.24 J4.A11@6102.36,728.35 ; J4.A11@6094.49,726.38 J4.A11@6099.61,726.38
PXI_AD19: J4.E10 U29.24 | length 442.4
  Top Layer w6: U29.24@5374.02,570.87 5482.28,570.87 5541.34,570.87 5582.87,612.39 5749.4,612.39 J4.E10@5784.65,647.64
PXI_AD20: J4.D10 U29.23 | length 717.6
  Top Layer w6: v1(5295.28,551.18) U29.23@5374.02,551.18
  Bottom Layer w6: v1(5295.28,551.18) 5492.13,551.18 5620.08,679.13 5831.89,679.13 J4.D10@5863.39,647.64 J4.D10@5863.39,652.36
PXI_AD21: J4.A10 U29.22 | length 763.9
  Top Layer w6: U29.22@5383.86,531.5 5551.18,531.5 5620.08,600.39 6052.36,600.39 J4.A10@6099.61,647.64
PXI_AD22: J4.E9 U29.21 | length 621.9
  Top Layer w6: v1(5295.28,511.81) U29.21@5374.02,511.81
  Bottom Layer w6: v1(5295.28,511.81) 5501.97,511.81 5595.47,605.32 5748.23,605.32 J4.E9@5784.65,568.9
PXI_AD23: J4.C9 U29.20 | length 599.9
  Top Layer w6: U29.20@5374.02,492.13 5580.71,492.13 5622.24,533.65 5906.88,533.65 J4.C9@5942.13,568.9
PXI_AD24: J4.E8 U29.16 | length 442.4
  Top Layer w6: U29.16@5374.02,413.39 5590.55,413.39 5632.08,454.91 5749.4,454.91 J4.E8@5784.65,490.16
PXI_AD25: J4.D8 U29.14 | length 537.5
  Top Layer w6: U29.14@5374.02,374.02 5590.55,374.02 5659.45,442.91 5779.53,442.91 5826.77,490.16 J4.D8@5863.39,490.16
PXI_AD26: J4.A8 U29.13 | length 939.3
  Top Layer w6: v1(5295.28,354.33) U29.13@5374.02,354.33
  Bottom Layer w6: v1(5295.28,354.33) 5551.18,354.33 5651.76,454.91 6064.36,454.91 J4.A8@6099.61,490.16
PXI_AD27: J4.E7 U29.12 | length 446
  Top Layer w6: U29.12@5374.02,334.65 5580.71,334.65 5620.08,374.02 5748.03,374.02 J4.E7@5787.4,413.39
PXI_AD28: J4.C7 U29.11 | length 765.5
  Top Layer w6: v1(5295.28,314.96) U29.11@5374.02,314.96
  Bottom Layer w6: v1(5295.28,314.96) 5580.71,314.96 5641.92,376.17 5906.88,376.17 J4.C7@5942.13,411.42
PXI_AD29: J4.B7 U29.10 | length 698.5
  Top Layer w6: U29.10@5374.02,295.28 5573.02,295.28 5639.76,362.02 5972.25,362.02 J4.B7@6023.62,413.39
PXI_AD30: J4.A7 U29.9 | length 939.3
  Top Layer w6: v1(5295.28,275.59) U29.9@5374.02,275.59
  Bottom Layer w6: v1(5295.28,275.59) 5580.71,275.59 5669.29,364.17 6052.36,364.17 J4.A7@6099.61,411.42
PXI_AD31: J4.E6 U29.7 | length 618.7
  Top Layer w6: v1(5295.28,236.22) U29.7@5374.02,236.22
  Bottom Layer w6: v1(5295.28,236.22) 5580.71,236.22 5639.76,295.28 5642.71,298.22 5750.19,298.22 J4.E6@5784.65,332.68 J4.E6@5784.65,322.05
PXI_C/BE0: J4.E21 U27.3 | length 482.5
  Top Layer w6: U27.3@5374.02,1397.64 5472.44,1397.64 5617.27,1542.46 5755.96,1542.46 J4.E21@5784.65,1513.78
PXI_C/BE1: J4.E18 U28.16 | length 507.7
  Top Layer w6: U28.16@5374.02,1043.31 5433.07,1043.31 5632.08,1242.32 5749.4,1242.32 J4.E18@5784.65,1277.56
PXI_C/BE2: J4.E11 U28.2 | length 427.8
  Top Layer w6: U28.2@5374.02,767.72 5531.5,767.72 5541.34,757.87 5753.15,757.87 J4.E11@5784.65,726.38
PXI_C/BE3: J4.A9 U29.18 | length 773.7
  Top Layer w6: U29.18@5374.02,452.76 5590.55,452.76 5659.45,521.65 6052.36,521.65 J4.A9@6099.61,568.9
PXI_CLK: J4.D6 U29.6 | length 541
  Top Layer w6: U29.6@5374.02,216.54 5580.71,216.54 5659.45,295.28 5826.77,295.28 J4.D6@5866.14,334.65
PXI_CLK10: J5.E17
PXI_DEVSEL: J4.A16 U28.10 | length 809.9
  Top Layer w6: U28.10@5374.02,925.2 5492.13,925.2 5639.76,1072.83 5651.76,1084.83 6065.15,1084.83 J4.A16@6102.36,1122.05
PXI_FRAME: J4.B15 U28.6 | length 731.1
  Top Layer w6: U28.6@5374.02,846.46 5511.81,846.46 5657.29,991.94 5972.25,991.94 J4.B15@6023.62,1043.31
PXI_GNT: J4.E5 U29.4 | length 446
  Top Layer w6: U29.4@5374.02,177.17 5580.71,177.17 5620.08,216.54 5748.03,216.54 J4.E5@5787.4,255.91
PXI_IDSEL: J4.B9 U29.19 | length 844.3
  Top Layer w6: v1(5295.28,472.44) U29.19@5374.02,472.44
  Bottom Layer w6: v1(5295.28,472.44) 5600.39,472.44 5668.17,540.21 5992.18,540.21 J4.B9@6020.87,568.9
PXI_INTA: J4.A3 U29.2 | length 745.4
  Top Layer w6: U29.2@5374.02,137.8 6062.99,137.8 J4.A3@6102.36,98.43 ; J4.A3@6099.61,95.67 J4.A3@6099.61,96.46
PXI_IRDY: J4.C15 U28.7 | length 640.7
  Top Layer w6: U28.7@5374.02,866.14 5501.97,866.14 5639.76,1003.94 5904.72,1003.94 J4.C15@5942.13,1041.34
PXI_PAR: J4.D18 U28.14 | length 602.7
  Top Layer w6: U28.14@5374.02,1003.94 5433.07,1003.94 v1(5639.76,1210.63)
  Bottom Layer w6: v1(5639.76,1210.63) 5669.29,1240.16 5825.98,1240.16 J4.D18@5863.39,1277.56
PXI_PERR: J4.E17 U28.12 | length 497.3
  Top Layer w6: U28.12@5374.02,964.57 5462.6,964.57 5661.61,1163.57 5750.19,1163.57 J4.E17@5777.56,1190.94
PXI_REQ: J4.A6 U29.5 | length 939.3
  Top Layer w6: v1(5295.28,196.85) U29.5@5374.02,196.85
  Bottom Layer w6: v1(5295.28,196.85) 5580.71,196.85 5670.08,286.22 6053.15,286.22 J4.A6@6099.61,332.68
PXI_RST: J4.C5 U29.3 | length 780.9
  Top Layer w6: v1(5295.28,157.48) U29.3@5374.02,157.48
  Bottom Layer w6: v1(5295.28,157.48) 5580.71,157.48 5629.92,206.69 5894.88,206.69 J4.C5@5942.13,253.94 ; J4.C5@5942.13,243.31 J4.C5@5942.13,253.94 ; J4.C5@5946.85,253.94 J4.C5@5942.13,253.94
PXI_SERR: J4.A18 U28.13 | length 847.1
  Top Layer w6: U28.13@5374.02,984.25 5445.31,984.25 5691.38,1230.32 6052.36,1230.32 J4.A18@6099.61,1277.56
PXI_START: J5.D17
PXI_STOP: J4.D16 U28.11 | length 588
  Top Layer w6: U28.11@5374.02,944.88 5474.84,944.88 5681.54,1151.57 5831.89,1151.57 J4.D16@5863.39,1120.08
PXI_TRDY: J4.E15 U28.9 | length 493
  Top Layer w6: U28.9@5374.02,905.51 5511.81,905.51 5679.13,1072.83 5753.15,1072.83 J4.E15@5784.65,1041.34
PXI_TRIG0: J5.B16
PXI_TRIG1: J5.A16
PXI_TRIG2: J5.A17
PXI_TRIG3: J5.A18
PXI_TRIG4: J5.B18
PXI_TRIG5: J5.C18
PXI_TRIG6: J5.E18
PXI_TRIG7: J5.E16
V16210: C121.2 D19.2 R116.2 U27.15 U28.15 U29.15 | length 1669.1
  Top Layer w10: v1(5265.75,1023.62) U28.15@5374.02,1023.62
  Top Layer w12: v1(5265.75,393.7) U29.15@5374.02,393.7 ; U27.15@5374.02,1633.86 v1(5442.91,1633.86)
  Bottom Layer w10: v1@5259.84,1017.72 v1(5265.75,1023.62)
  Bottom Layer w12: C121.2@5246.06,935.04 5246.06,413.39 v1(5265.75,393.7) ; R116.2@5246.06,1397.64 5246.06,1043.31 v1(5265.75,1023.62) C121.2@5265.75,954.72 ; R116.2@5259.84,1397.64 D19.2@5259.84,1525.59 ; D19.2@5275.59,1525.59 5275.59,1584.65 5324.8,1633.86 v1(5442.91,1633.86)
VCCA_PLL1: C3.1 C5.2 C6.2 L1.2 U1.27 | length 499.8
  Top Layer w10: U1.27@3433.07,1318.9 v1(3513.78,1318.9)
  Bottom Layer w10: v1(3513.78,1318.9) 3568.9,1318.9 C6.2@3572.83,1322.83 C5.2@3671.26,1322.83 3917.32,1322.83 L1.2@3927.17,1312.99
VCCA_PLL2: C7.1 C9.2 C10.2 L2.2 U1.154 | length 515.6
  Top Layer w10: v1(4714.57,1309.06) 4724.41,1318.9 U1.154@4795.28,1318.9
  Bottom Layer w10: L2.2@4301.18,1312.99 C7.1@4446.85,1312.99 ; C7.1@4468.5,1309.06 4492.13,1332.68 C9.2@4557.09,1332.68 C10.2@4645.67,1332.68 ; C10.2@4659.45,1318.9 C10.2@4645.67,1332.68 ; v1(4714.57,1309.06) 4669.29,1309.06 C10.2@4645.67,1332.68
pads on no net: J1.101 J1.102 J2.6 J2.7 J2.8 J4.A2 J4.A4 J4.A5 J4.A15 J4.A17 J4.A19 J4.A21 J4.A23 J4.B1 J4.B3 J4.B5 J4.B17 J4.B25 J4.C1 J4.C2 J4.C3 J4.C4 J4.C6 J4.C8 J4.C10 J4.C16 J4.C17 J4.C18 J4.C20 J4.C22 J4.C24 J4.C25 J4.D1 J4.D4 J4.D25 J4.E3 J4.E4 J4.E16 J4.E24 J4.F2 J4.F4 J4.F6 J4.F8 J4.F10 J4.F12 J4.F14 J4.F16 J4.F18 J4.F20 J4.F22 J4.F24 J5.A1 J5.A2 J5.A3 J5.A4 J5.A5 J5.A6 J5.A7 J5.A8 J5.A9 J5.A10 J5.A11 J5.A12 J5.A13 J5.A14 J5.A15 J5.A19 J5.A20 J5.A21 J5.A22 J5.B2 J5.B4 J5.B5 J5.B6 J5.B8 J5.B10 J5.B12 J5.B14 J5.B19 J5.B20 J5.B21 J5.B22 J5.C1 J5.C2 J5.C3 J5.C4 J5.C5 J5.C6 J5.C7 J5.C8 J5.C9 J5.C10 J5.C11 J5.C12 J5.C13 J5.C14 J5.C15 J5.C16 J5.C17 J5.C19 J5.C20 J5.C21 J5.C22 J5.D1 J5.D2 J5.D3 J5.D5 J5.D7 J5.D9 J5.D11 J5.D13 J5.D15 J5.D19 J5.D21 J5.D22 J5.E1 J5.E2 J5.E3 J5.E4 J5.E5 J5.E6 J5.E7 J5.E8 J5.E9 J5.E10 J5.E11 J5.E12 J5.E13 J5.E14 J5.E15 J5.E19 J5.E20 J5.E21 J5.E22 J5.F2 J5.F4 J5.F6 J5.F8 J5.F10 J5.F12 J5.F14 J5.F16 J5.F18 J5.F20 J5.F22 U1.19 U1.20 U1.21 U1.23 U1.32 U1.38 U1.39 U1.73 U1.74 U1.75 U1.76 U1.77 U1.78 U1.79 U1.82 U1.83 U1.84 U1.85 U1.86 U1.87 U1.93 U1.98 U1.106 U1.133 U1.152 U1.156 U1.168 U1.196 U1.197 U1.213 U1.226 U1.227 U1.228 U1.233 U1.234 U1.235 U1.236 U9.1 U10.1 U11.1 U12.1 U13.1 U14.1 U15.1 U16.1 U17.1 U18.1 U19.1 U20.1 U21.1 U22.1 U23.1 U24.1 U27.1 U28.1 U29.1 VR1.4 VR2.4 X1.1

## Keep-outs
Keep-Out Layer:
  lines w7.87: -140.55,-218.5 6079.92,-218.5 6158.66,-139.76 6158.66,3642.05 6082.2,3718.5 -140.55,3718.5 -140.55,-218.5

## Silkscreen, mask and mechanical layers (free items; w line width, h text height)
Top Overlay:
  text "5V" at 4586.61,3562.99 h40
  text "Relay 5VDC to 60VDC" at 1151.57,3464.57 h40
  text "1.5V" at 4596.46,2972.44 h40
  text "3.3V" at 5423.23,2962.05 h40
  text "5V DC" at 4970.47,2893.7 h40
  text "5V OC" at 4596.46,2814.96 h40
  text "O5_1" at 3110.24,2785.43 h40
  text "OC5_1" at 5029.53,2145.67 h40
  text "O27_1" at 3100.39,2125.98 h40
  text "SCSI-100" at 354.33,1555.12 h40 r90
  text "I5_9" at 1633.86,1407.48 h40
  text "Isolation 5V" at 570.87,1131.89 h40 r90
  text "AS" at 3277.56,1092.52 h40 r90
  text "I5_1" at 1633.86,787.4 h40
  text "JTAG" at 3267.72,246.06 h40 r90
  text "Isolation 27V" at 590.55,167.32 h40 r90
  text "I27_1" at 1614.17,137.8 h40
  text "PXI Digital I/O V0.1 2013/7/22" at 137.8,-59.06 h40

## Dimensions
-140.55,-218.5 to 6158.66,-120.08 on Mechanical 13
-140.55,-218.5 to -140.55,3718.5 on Mechanical 13
0,0 to 0,3500 on Mechanical 13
